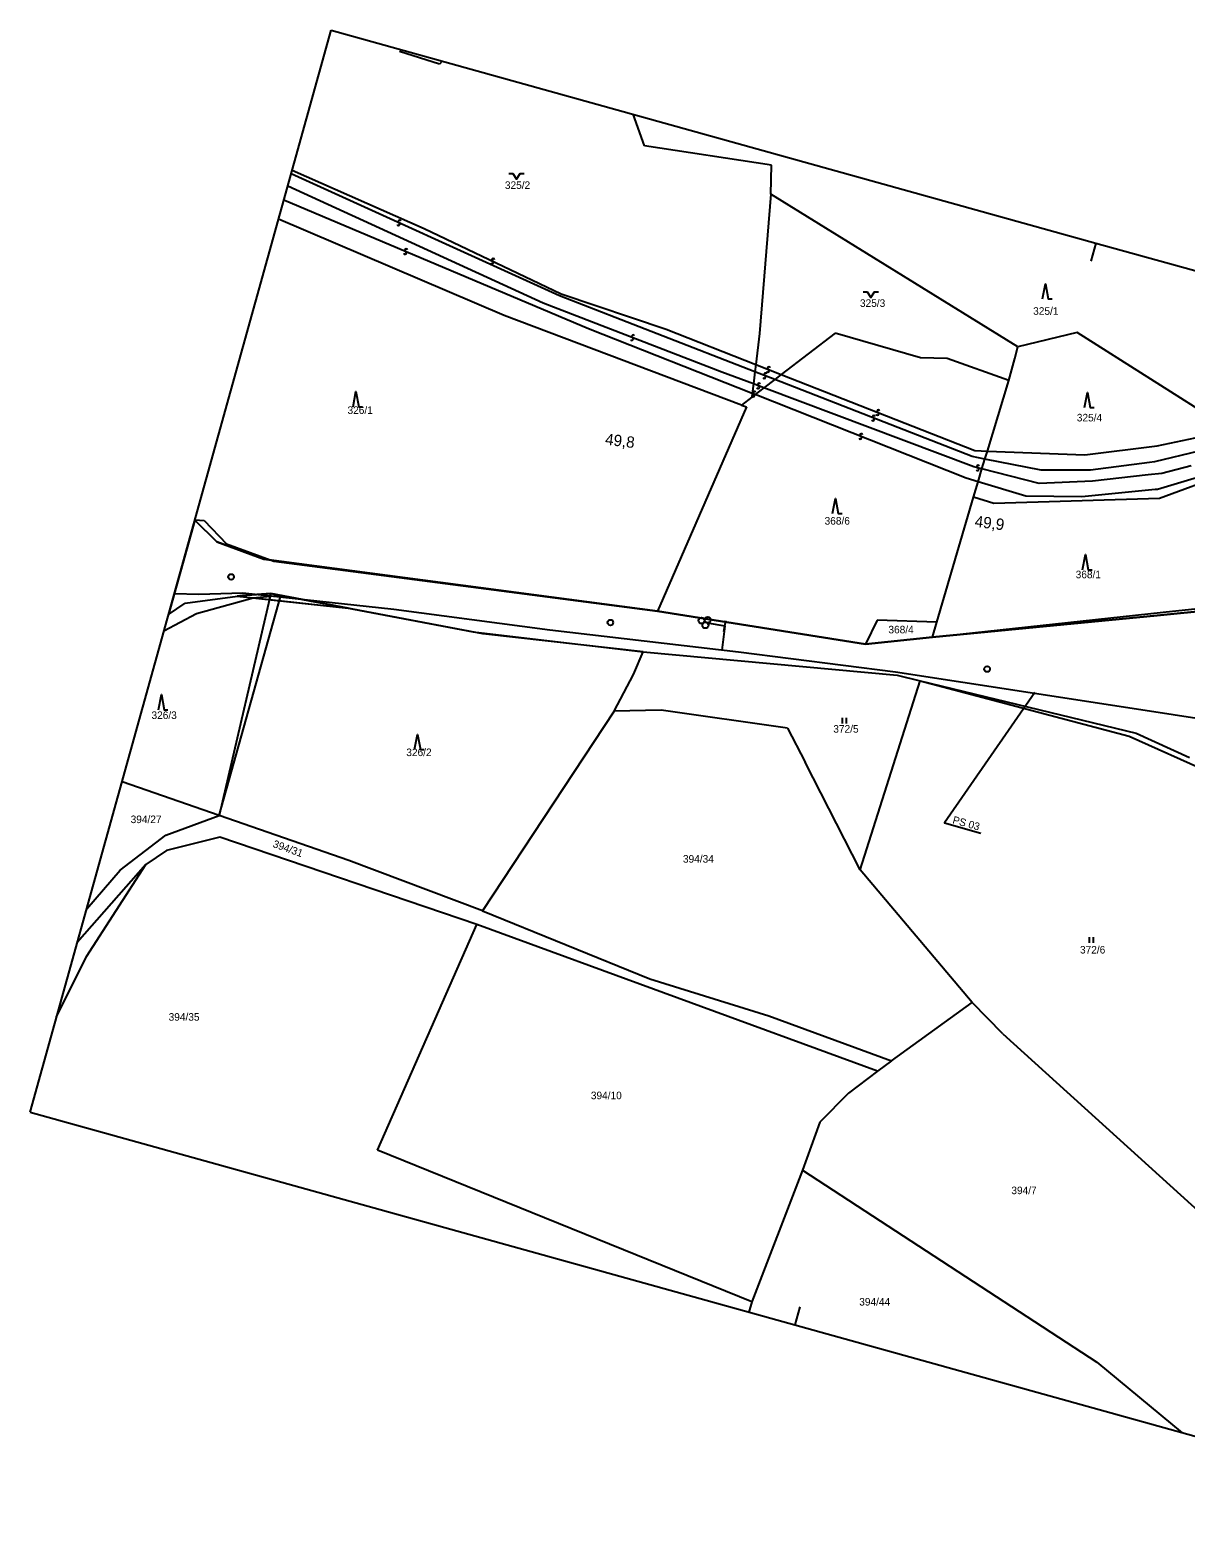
# Model space of a CAD drawing. Extents: x -678084 to -677195, y -1006706 to -1006195.
# Drawn here: x -678084.3 to -677778.6, y -1006593.3 to -1006194.5 of the extents above; entities that cross this region are included whole.
import ezdxf

# ---------------------------------------------------------------- set-up
doc = ezdxf.new("R2010")
doc.units = 0
for name, color, linetype in [('I_2_4_předběžný_vykres - Dočasný zábor - do 1 roku - PUPFL', 7, 'Continuous'), ('I_2_4_předběžný_vykres - SŽDC', 7, 'Continuous'), ('I_2_4_předběžný_vykres - VBř', 7, 'Continuous'), ('kilometráž - Vrstva 7', 7, 'Continuous'), ('koor - SSZT_nové', 7, 'Continuous'), ('MapaKN - Mladejov+Strelec_dosavani+nova_situace - Vrstva 1', 7, 'Continuous'), ('MapaKN - Mladejov+Strelec_dosavani+nova_situace - Vrstva 11', 7, 'Continuous'), ('MapaKN - Mladejov+Strelec_dosavani+nova_situace - Vrstva 18', 7, 'Continuous'), ('MapaKN - Mladejov+Strelec_dosavani+nova_situace - Vrstva 25', 7, 'Continuous'), ('MapaKN - Mladejov+Strelec_dosavani+nova_situace - Vrstva 4', 7, 'Continuous'), ('MapaKN - původní vrstava 1', 7, 'Continuous'), ('popis', 7, 'Continuous'), ('ramy - Sekce lichá', 7, 'Continuous')]:
    doc.layers.add(name, color=color, linetype=linetype)

msp = doc.modelspace()

# ---------------------------------------------------------------- linework, layer by layer
at = {"layer": 'I_2_4_předběžný_vykres - Dočasný zábor - do 1 roku - PUPFL'}
for p, q in [((-678028.13, -1006344.03), (-678029.55, -1006344.22)), ((-678029.55, -1006344.22), (-678021.01, -1006345.14)), ((-678020.64, -1006343.54), (-678028.13, -1006344.03)), ((-678021.01, -1006345.14), (-678020.64, -1006343.54)), ((-678020.64, -1006343.54), (-678021.01, -1006345.14)), ((-678000.24, -1006347.39), (-678020.64, -1006343.54)), ((-678021.01, -1006345.14), (-678000.24, -1006347.39))]:
    msp.add_line(p, q, dxfattribs=at)
msp.add_lwpolyline([(-678029.55, -1006344.22), (-678000.24, -1006347.39)], dxfattribs=at)
at = {"layer": 'I_2_4_předběžný_vykres - SŽDC'}
for p, q in [((-678040.79, -1006324.16), (-678047.72, -1006349.06)), ((-678034.98, -1006329.89), (-678040.79, -1006324.16)), ((-678022.51, -1006334.41), (-678034.98, -1006329.89)), ((-677918.4, -1006348.18), (-678022.51, -1006334.41)), ((-678043.36, -1006346.1), (-678028.13, -1006344.03)), ((-678028.13, -1006344.03), (-678020.64, -1006343.54)), ((-678020.64, -1006343.54), (-677967.17, -1006353.62)), ((-678047.72, -1006349.06), (-678043.36, -1006346.1)), ((-677863.38, -1006356.93), (-677918.4, -1006348.18)), ((-677771.99, -1006347.9), (-677786.18, -1006349.31)), ((-677786.18, -1006349.31), (-677845.59, -1006355.04)), ((-677967.17, -1006353.62), (-677922.14, -1006358.97)), ((-677845.59, -1006355.04), (-677863.38, -1006356.93)), ((-677922.14, -1006358.97), (-677854.94, -1006365.15)), ((-677854.94, -1006365.15), (-677848.86, -1006366.62)), ((-677848.86, -1006366.62), (-677793.6, -1006381.25)), ((-677793.6, -1006381.25), (-677772.38, -1006390.75))]:
    msp.add_line(p, q, dxfattribs=at)
at = {"layer": 'I_2_4_předběžný_vykres - VBř'}
msp.add_lwpolyline([(-678029.55, -1006344.22), (-678000.24, -1006347.39), (-678020.64, -1006343.54)], close=True, dxfattribs=at)
at = {"layer": 'kilometráž - Vrstva 7'}
for centre in [(-678031.17, -1006339.12), (-677930.85, -1006351.19), (-677831.17, -1006363.51)]:
    msp.add_circle(centre, 0.75, dxfattribs=at)
at = {"layer": 'koor - SSZT_nové'}
for p, q in [((-677905.23, -1006351.31), (-677900.56, -1006352.09)), ((-677900.56, -1006352.12), (-677901.34, -1006358.47)), ((-677900.79, -1006353.55), (-677900.34, -1006350.68))]:
    msp.add_line(p, q, dxfattribs=at)
msp.add_lwpolyline([(-678046.18, -1006343.51), (-678039.76, -1006343.69), (-678028.1, -1006343.37), (-677988.11, -1006347.69), (-677946.88, -1006353.16), (-677896.95, -1006358.97), (-677855.43, -1006364.26), (-677800.81, -1006372.62), (-677763.07, -1006378.4), (-677730.99, -1006381.64), (-677703.96, -1006383), (-677678.22, -1006388.09), (-677650.5, -1006395.33), (-677540.71, -1006433.07)], dxfattribs=at)
for centre in [(-677906.74, -1006350.69), (-677905.72, -1006351.93), (-677905.1, -1006350.5)]:
    msp.add_circle(centre, 0.792, dxfattribs=at)
at = {"layer": 'MapaKN - Mladejov+Strelec_dosavani+nova_situace - Vrstva 1'}
for points in [[(-677976.03, -1006203.56), (-677986.61, -1006200.22)], [(-677975.31, -1006202.72), (-677976.03, -1006203.56)], [(-677921.81, -1006225.09), (-677924.83, -1006216.77)], [(-677888.18, -1006230.26), (-677921.81, -1006225.09)], [(-677888.41, -1006237.95), (-677888.18, -1006230.26)], [(-677888.41, -1006237.95), (-677891.42, -1006274.73)], [(-677823.04, -1006278.3), (-677888.41, -1006237.95)], [(-677958.9, -1006269.98), (-678018.64, -1006244.55)], [(-677896.13, -1006293.68), (-677958.9, -1006269.98)], [(-677891.42, -1006274.73), (-677892.39, -1006282.96)], [(-677871.38, -1006274.64), (-677885.64, -1006285.61)], [(-677848.81, -1006281.2), (-677871.38, -1006274.64)], [(-677807.32, -1006274.53), (-677823.04, -1006278.3)], [(-677768.42, -1006299.16), (-677807.32, -1006274.53)], [(-677823.86, -1006281.33), (-677823.04, -1006278.3)], [(-677892.39, -1006282.96), (-677892.62, -1006284.91)], [(-677841.78, -1006281.38), (-677848.81, -1006281.2)], [(-677825.43, -1006287.18), (-677841.78, -1006281.38)], [(-677825.43, -1006287.18), (-677823.86, -1006281.33)], [(-677893, -1006288.11), (-677893.3, -1006290.62)], [(-677892.62, -1006284.91), (-677893, -1006288.11)], [(-677887.38, -1006286.95), (-677890.24, -1006289.15)], [(-677885.64, -1006285.61), (-677887.38, -1006286.95)], [(-677831.1, -1006305.85), (-677825.43, -1006287.18)], [(-677893.42, -1006291.6), (-677896.13, -1006293.68)], [(-677893.3, -1006290.62), (-677893.42, -1006291.6)], [(-677892.54, -1006290.92), (-677893.42, -1006291.6)], [(-677890.24, -1006289.15), (-677892.54, -1006290.92)], [(-677894.83, -1006294.13), (-677918.4, -1006348.18)], [(-677896.13, -1006293.68), (-677894.83, -1006294.13)], [(-677832.54, -1006310.59), (-677831.75, -1006307.98)], [(-677831.75, -1006307.98), (-677831.1, -1006305.85)], [(-677833.56, -1006313.95), (-677832.54, -1006310.59)], [(-677767.82, -1006311.9), (-677785.59, -1006318.42)], [(-677834.8, -1006318.04), (-677833.56, -1006313.95)], [(-677844.44, -1006351.14), (-677834.8, -1006318.04)], [(-677829.42, -1006319.73), (-677834.8, -1006318.04)], [(-677785.59, -1006318.42), (-677829.42, -1006319.73)], [(-677918.4, -1006348.18), (-677863.38, -1006356.93)], [(-677860.25, -1006350.53), (-677863.38, -1006356.93)], [(-677844.44, -1006351.14), (-677860.25, -1006350.53)], [(-677845.59, -1006355.04), (-677844.44, -1006351.14)], [(-677863.38, -1006356.93), (-677845.59, -1006355.04)], [(-677924.77, -1006364.95), (-677922.14, -1006358.97)], [(-677922.14, -1006358.97), (-677854.94, -1006365.15)], [(-677929.87, -1006374.61), (-677924.77, -1006364.95)], [(-677864.77, -1006416.62), (-677848.86, -1006366.62)], [(-677854.94, -1006365.15), (-677848.86, -1006366.62)], [(-677929.87, -1006374.61), (-677964.64, -1006427.47)], [(-677917.37, -1006374.36), (-677929.87, -1006374.61)], [(-677883.97, -1006379.13), (-677917.37, -1006374.36)], [(-677883.97, -1006379.13), (-677879.31, -1006388.13)], [(-677864.77, -1006416.62), (-677879.31, -1006388.13)], [(-678034.32, -1006402.24), (-678060.04, -1006393.32)], [(-678048.48, -1006407.43), (-678034.32, -1006402.24)], [(-678000, -1006414.15), (-678034.32, -1006402.24)], [(-678060.57, -1006416.67), (-678048.48, -1006407.43)], [(-678034.19, -1006407.98), (-678048.29, -1006411.44)], [(-677966.17, -1006431.09), (-678034.19, -1006407.98)], [(-678048.29, -1006411.44), (-678053.78, -1006415.18)], [(-678053.78, -1006415.18), (-678071.86, -1006435.82)], [(-678069.44, -1006439.48), (-678053.78, -1006415.18)], [(-677964.64, -1006427.47), (-678000, -1006414.15)], [(-678069.39, -1006426.91), (-678060.57, -1006416.67)], [(-677835.11, -1006451.68), (-677864.77, -1006416.62)], [(-677964.64, -1006427.47), (-677920.4, -1006445.43)], [(-677992.47, -1006490.71), (-677966.17, -1006431.09)], [(-677860.14, -1006469.84), (-677966.17, -1006431.09)], [(-678077.34, -1006455.51), (-678069.44, -1006439.48)], [(-677920.4, -1006445.43), (-677888.93, -1006455.2)], [(-677856.48, -1006467.11), (-677835.11, -1006451.68)], [(-677827.03, -1006459.97), (-677835.11, -1006451.68)], [(-677888.93, -1006455.2), (-677856.48, -1006467.11)], [(-677827.03, -1006459.97), (-677755.57, -1006524.69)], [(-677856.48, -1006467.11), (-677860.14, -1006469.84)], [(-677860.14, -1006469.84), (-677867.89, -1006475.63)], [(-677867.89, -1006475.63), (-677875.42, -1006483.33)], [(-677875.42, -1006483.33), (-677880.02, -1006495.99)], [(-677893.46, -1006530.84), (-677992.47, -1006490.71)], [(-677880.02, -1006495.99), (-677893.46, -1006530.84)], [(-677880.02, -1006495.99), (-677802.12, -1006546.8)], [(-677893.46, -1006530.84), (-677894.22, -1006533.57)], [(-677802.12, -1006546.8), (-677779.57, -1006565.47)]]:
    msp.add_lwpolyline(points, dxfattribs=at)
at = {"layer": 'MapaKN - Mladejov+Strelec_dosavani+nova_situace - Vrstva 11'}
for points in [[(-678040.79, -1006324.16), (-678034.98, -1006329.89)], [(-678034.98, -1006329.89), (-678022.51, -1006334.41)], [(-678022.51, -1006334.41), (-677918.4, -1006348.18)], [(-678043.36, -1006346.1), (-678028.13, -1006344.03)], [(-678020.64, -1006343.54), (-678034.32, -1006402.24)], [(-678028.13, -1006344.03), (-678020.64, -1006343.54)], [(-678020.64, -1006343.54), (-677967.17, -1006353.62)], [(-678047.72, -1006349.06), (-678043.36, -1006346.1)], [(-677786.18, -1006349.31), (-677771.99, -1006347.9)], [(-677845.59, -1006355.04), (-677786.18, -1006349.31)], [(-677967.17, -1006353.62), (-677922.14, -1006358.97)], [(-677848.86, -1006366.62), (-677793.6, -1006381.25)], [(-677793.6, -1006381.25), (-677772.38, -1006390.75)]]:
    msp.add_lwpolyline(points, dxfattribs=at)
at = {"layer": 'MapaKN - Mladejov+Strelec_dosavani+nova_situace - Vrstva 25'}
for points in [[(-677957.68, -1006232.41), (-677956.68, -1006232.41), (-677955.68, -1006233.91), (-677954.68, -1006232.41), (-677953.68, -1006232.41)], [(-677863.95, -1006263.73), (-677862.95, -1006263.73), (-677861.95, -1006265.23), (-677860.95, -1006263.73), (-677859.95, -1006263.73)], [(-677816.49, -1006265.61), (-677815.74, -1006261.61), (-677814.99, -1006265.61), (-677813.99, -1006265.61)], [(-677998.9, -1006294.14), (-677998.15, -1006290.14), (-677997.4, -1006294.14), (-677996.4, -1006294.14)], [(-677805.39, -1006294.36), (-677804.64, -1006290.36), (-677803.89, -1006294.36), (-677802.89, -1006294.36)], [(-677872.05, -1006322.36), (-677871.3, -1006318.36), (-677870.55, -1006322.36), (-677869.55, -1006322.36)], [(-677805.91, -1006337.23), (-677805.16, -1006333.23), (-677804.41, -1006337.23), (-677803.41, -1006337.23)], [(-678050.38, -1006374.27), (-678049.63, -1006370.27), (-678048.88, -1006374.27), (-678047.88, -1006374.27)], [(-677869.42, -1006377.93), (-677869.42, -1006376.43)], [(-677868.38, -1006377.93), (-677868.38, -1006376.43)], [(-677982.62, -1006384.79), (-677981.87, -1006380.79), (-677981.12, -1006384.79), (-677980.12, -1006384.79)], [(-677804.09, -1006435.86), (-677804.09, -1006434.36)], [(-677803.05, -1006435.86), (-677803.05, -1006434.36)]]:
    msp.add_lwpolyline(points, dxfattribs=at)
for centre, radius, start, end in [((-677986.62, -1006245.16), 0.369, 12.8319, 244.791), ((-677986.93, -1006245.82), 0.367, 192.5974, 65.0402), ((-677984.86, -1006252.76), 0.368, 14.451, 246.3159), ((-677985.15, -1006253.44), 0.368, 194.436, 66.7815), ((-677962.15, -1006255.98), 0.369, 191.8902, 63.7046), ((-677961.83, -1006255.32), 0.367, 12.0714, 244.2036), ((-677925.13, -1006276.2), 0.367, 196.1847, 68.6047), ((-677924.86, -1006275.52), 0.368, 16.416, 248.3788), ((-677889.16, -1006284.63), 0.369, 195.9256, 67.869), ((-677888.88, -1006283.95), 0.368, 15.5018, 248.1137), ((-677891.75, -1006288.97), 0.367, 196.5212, 68.9518), ((-677891.49, -1006288.29), 0.368, 16.7143, 248.8683), ((-677890.14, -1006286.27), 0.368, 195.832, 68.2571), ((-677889.86, -1006285.59), 0.368, 15.9241, 248.0275), ((-677893.06, -1006291.11), 0.368, 195.4781, 68.1123), ((-677892.78, -1006290.43), 0.369, 15.9241, 247.8897), ((-677861.13, -1006296.79), 0.368, 15.9241, 248.0333), ((-677860.19, -1006296.01), 0.369, 195.9256, 67.869), ((-677859.91, -1006295.33), 0.368, 15.5018, 248.1137), ((-677861.41, -1006297.47), 0.368, 195.6921, 68.1123), ((-677864.76, -1006302.3), 0.368, 195.4781, 68.1123), ((-677864.48, -1006301.62), 0.369, 15.9241, 247.8897), ((-677833.71, -1006310.67), 0.367, 203.0588, 75.3601), ((-677833.52, -1006309.95), 0.369, 23.158, 255.0329)]:
    msp.add_arc(centre, radius, start, end, dxfattribs=at)
at = {"layer": 'MapaKN - Mladejov+Strelec_dosavani+nova_situace - Vrstva 4'}
for points in [[(-677944.28, -1006264.77), (-678015.3, -1006232.54)], [(-678015.03, -1006231.58), (-677980.14, -1006246.99)], [(-677948.63, -1006266.74), (-678016.19, -1006235.75)], [(-677936.64, -1006273.48), (-678017.24, -1006239.51)], [(-677980.14, -1006246.99), (-677943.84, -1006264.3)], [(-677892.62, -1006284.91), (-677944.28, -1006264.77)], [(-677943.84, -1006264.3), (-677916.13, -1006273.63)], [(-677901.37, -1006284.97), (-677948.63, -1006266.74)], [(-677893.3, -1006290.62), (-677936.64, -1006273.48)], [(-677916.13, -1006273.63), (-677892.39, -1006282.96)], [(-677892.39, -1006282.96), (-677885.64, -1006285.61)], [(-677893, -1006288.11), (-677901.37, -1006284.97)], [(-677890.24, -1006289.15), (-677893, -1006288.11)], [(-677887.38, -1006286.95), (-677892.62, -1006284.91)], [(-677835.16, -1006307.31), (-677887.38, -1006286.95)], [(-677885.64, -1006285.61), (-677834.46, -1006305.72)], [(-677892.54, -1006290.92), (-677893.3, -1006290.62)], [(-677836.7, -1006313), (-677892.54, -1006290.92)], [(-677834.7, -1006310.04), (-677890.24, -1006289.15)], [(-677805.34, -1006306.84), (-677786.23, -1006304.47)], [(-677786.23, -1006304.47), (-677776.16, -1006302.31)], [(-677831.75, -1006307.98), (-677835.16, -1006307.31)], [(-677834.46, -1006305.72), (-677831.1, -1006305.85)], [(-677816.85, -1006310.88), (-677831.75, -1006307.98)], [(-677831.1, -1006305.85), (-677805.34, -1006306.84)], [(-677775.2, -1006305.91), (-677786.92, -1006308.74)], [(-677832.54, -1006310.59), (-677834.7, -1006310.04)], [(-677817.37, -1006314.41), (-677832.54, -1006310.59)], [(-677803.8, -1006310.86), (-677816.85, -1006310.88)], [(-677788.2, -1006308.9), (-677803.8, -1006310.86)], [(-677788.59, -1006312.15), (-677803.29, -1006313.8)], [(-677784.93, -1006311.74), (-677788.59, -1006312.15)], [(-677786.92, -1006308.74), (-677788.2, -1006308.9)], [(-677766.05, -1006310.02), (-677786.08, -1006315.99)], [(-677777.23, -1006309.76), (-677784.93, -1006311.74)], [(-677833.56, -1006313.95), (-677836.7, -1006313)], [(-677820.96, -1006317.78), (-677833.56, -1006313.95)], [(-677803.29, -1006313.8), (-677817.37, -1006314.41)], [(-677786.72, -1006316.05), (-677806.11, -1006317.95)], [(-677786.08, -1006315.99), (-677786.72, -1006316.05)], [(-677806.11, -1006317.95), (-677820.96, -1006317.78)]]:
    msp.add_lwpolyline(points, dxfattribs=at)
at = {"layer": 'MapaKN - původní vrstava 1'}
for points in [[(-678040.76, -1006324.04), (-678038.33, -1006324.2)], [(-678038.33, -1006324.2), (-678032.36, -1006330.42)], [(-678032.36, -1006330.42), (-678019.89, -1006334.95)], [(-678019.89, -1006334.95), (-677918.4, -1006348.18)], [(-678034.32, -1006402.24), (-678018.03, -1006344.08)], [(-678018.03, -1006344.08), (-678025.34, -1006344.76)], [(-677964.57, -1006354.22), (-678018.03, -1006344.08)], [(-678025.34, -1006344.76), (-678040.3, -1006348.88)], [(-677845.59, -1006355.04), (-677784.57, -1006348.48)], [(-677784.57, -1006348.48), (-677770.39, -1006346.95)], [(-678040.3, -1006348.88), (-678048.94, -1006353.45)], [(-677922.14, -1006358.97), (-677964.57, -1006354.22)], [(-677848.86, -1006366.62), (-677791.71, -1006380.48)], [(-677791.71, -1006380.48), (-677777.64, -1006386.87)]]:
    msp.add_lwpolyline(points, dxfattribs=at)
at = {"layer": 'popis'}
msp.add_lwpolyline([(-677818.56, -1006369.7), (-677842.44, -1006404.21), (-677832.85, -1006406.88)], dxfattribs=at)
at = {"layer": 'ramy - Sekce lichá'}
for p, q in [((-678084.34, -1006480.66), (-678004.72, -1006194.53)), ((-678004.72, -1006194.53), (-677802.41, -1006250.83)), ((-677802.41, -1006250.83), (-677803.75, -1006255.65)), ((-677802.41, -1006250.83), (-677600.1, -1006307.13)), ((-678084.34, -1006480.66), (-677882.03, -1006536.96)), ((-677880.69, -1006532.14), (-677882.03, -1006536.96)), ((-677882.03, -1006536.96), (-677679.72, -1006593.26))]:
    msp.add_line(p, q, dxfattribs=at)

# ---------------------------------------------------------------- texts
at = {"layer": 'kilometráž - Vrstva 7'}
for s, rotation, p in [('49,8', 352.9667, (-677932.36, -1006304.13)), ('49,9', 352.9063, (-677834.59, -1006325.86))]:
    msp.add_text(s, height=3, rotation=rotation, dxfattribs=at).set_placement(p)
at = {"layer": 'MapaKN - Mladejov+Strelec_dosavani+nova_situace - Vrstva 18'}
for s, p in [('325/2', (-677958.75, -1006236.53)), ('325/3', (-677864.82, -1006267.72)), ('325/1', (-677819, -1006269.81)), ('326/1', (-678000.38, -1006296.03)), ('325/4', (-677807.45, -1006298.01)), ('368/6', (-677874.17, -1006325.3)), ('368/1', (-677807.75, -1006339.48)), ('368/4', (-677857.29, -1006354.06)), ('326/3', (-678052.24, -1006376.7)), ('372/5', (-677871.87, -1006380.32)), ('326/2', (-677984.83, -1006386.52)), ('394/27', (-678057.76, -1006404.24)), ('394/34', (-677911.65, -1006414.7)), ('372/6', (-677806.61, -1006438.73)), ('394/35', (-678047.71, -1006456.5)), ('394/10', (-677936.01, -1006477.26)), ('394/7', (-677824.77, -1006502.37)), ('394/44', (-677865.01, -1006531.83))]:
    msp.add_text(s, height=2, dxfattribs=at).set_placement(p)
msp.add_text('394/31', height=2, rotation=340.4027, dxfattribs=at).set_placement((-678020.31, -1006410.53))
at = {"layer": 'popis'}
msp.add_text('PS 03', height=2, rotation=344.4496, dxfattribs=at).set_placement((-677840.47, -1006404.26))

doc.saveas('drawing.dxf')
